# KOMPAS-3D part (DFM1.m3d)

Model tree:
1. Эскиз:1
2. Операция выдавливания:1
     Расстояние 1 = 5.8
3. Эскиз:2
4. Эскиз:3
5. Эскиз:4
6. Эскиз:5
7. Эскиз:6
8. Эскиз:7
9. Вырезать элемент выдавливания:1
     Расстояние 1 = 0.85; Угол 1 = 45
10. Вырезать элемент выдавливания:2
     Расстояние 1 = 0.85; Угол 1 = 45
11. Вырезать элемент выдавливания:3
     Расстояние 1 = 0.85; Угол 1 = 45
12. Операция выдавливания:2
     Расстояние 1 = 0.85; Угол 1 = 45
13. Операция выдавливания:3
     Расстояние 1 = 0.85; Угол 1 = 45
14. Операция выдавливания:4
     Расстояние 1 = 0.85; Угол 1 = 45
15. Эскиз:8
16. Эскиз:9
17. Эскиз:10
18. Эскиз:11
19. Эскиз:12
20. Эскиз:13
21. Операция выдавливания:5
     Расстояние 1 = 0.85; Угол 1 = 45
22. Операция выдавливания:6
     Расстояние 1 = 0.85; Угол 1 = 45
23. Операция выдавливания:7
     Расстояние 1 = 0.85; Угол 1 = 45
24. Вырезать элемент выдавливания:4
     Расстояние 1 = 0.85; Угол 1 = 45
25. Вырезать элемент выдавливания:5
     Расстояние 1 = 0.85; Угол 1 = 45
26. Вырезать элемент выдавливания:6
     Расстояние 1 = 0.85; Угол 1 = 45
27. Массив по концентрической сетке:1  (with: Операция выдавливания:5, Операция выдавливания:6, Операция выдавливания:7, Вырезать элемент выдавливания:4, Вырезать элемент выдавливания:5, Вырезать элемент выдавливания:6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)  (6 pattern instances)
     Геометрический массив = 5; Шаг 2 = 360; Номер 2 = 1
28. Скругление:1
     Радиус = 2.9
29. Фаска:1
     Угол = 45; Длина 1 = 0.6; Длина 2 = 0.6
30. Фаска:2
     Угол = 40; Длина 1 = 0.8; Длина 2 = 0.67128
31. Эскиз:14
32. Операция выдавливания:8
     Расстояние 1 = 2.3
